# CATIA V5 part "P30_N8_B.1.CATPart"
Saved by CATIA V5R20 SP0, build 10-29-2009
Part number: P30_N8_B.1
Nomenclature: P30_N8_B
Source: Unknown
Bounding box of the stored display mesh (mm): x -15 to 15, y -15 to 15, z 0 to 530
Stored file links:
  C:\Users\halimelbaba\Documents\cmv\plan  d\P30_N8_B.1.CATPart
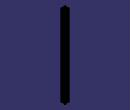
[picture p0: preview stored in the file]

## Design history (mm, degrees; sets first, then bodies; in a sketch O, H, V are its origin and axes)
Body1 "MANIFOLD_SOLID_BREP #6353" (main body)
  Solid1: solid without history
